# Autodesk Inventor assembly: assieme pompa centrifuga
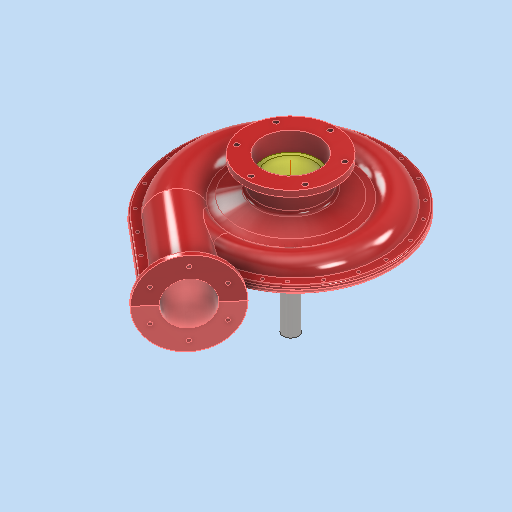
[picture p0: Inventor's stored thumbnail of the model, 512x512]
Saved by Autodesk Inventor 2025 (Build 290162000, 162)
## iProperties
Created: 2025-04
Part Number: assieme pompa centrifuga
Document SubType Name: Assembly
Designer: R5800u
Author: R5800u
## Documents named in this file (9)
- C:\Users\R5800u\Desktop\pompa centrifuga\assieme pompa centrifuga.iam
- C:\Users\R5800u\Desktop\pompa centrifuga\pompa centrifuga.ipt
- C:\Users\R5800u\Desktop\pompa centrifuga\cassa.ipt
- C:\Users\R5800u\Desktop\pompa centrifuga\cassa2.ipt
- C:\Users\R5800u\Desktop\pompa centrifuga\albero_20mm.ipt
- C:\Users\R5800u\Documents\Inventor\Content Center Files\R2025\it-IT\BS 290 SKF(30)\BS 290 SKF - SKF 6004.ipt
- C:\Users\R5800u\Documents\Inventor\Content Center Files\R2025\it-IT\DIN 7603 A\DIN 7603 - A20 x 24  (lt).ipt
- C:\Users\R5800u\Desktop\pompa centrifuga\oring 20mm.ipt
- C:\Users\R5800u\Documents\Inventor\Content Center Files\R2025\it-IT\AS 1420\AS 1420 - 1973 - M8 x 35.ipt
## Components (10 placed, 8 different names)
1. pompa centrifuga:1 — Coincidente:1, Allineato:1, Coincidente:6
2. cassa:1 — Coincidente:1, Allineato:1, Angolo:1, Coincidente:2, Coincidente:3, Allineato:2
3. cassa2:1 — Coincidente:2, Coincidente:3, Allineato:2, Allineato:3, Rotazionale:1, Rotazionale:3, Rotazionale:4
4. albero_20mm:1 — Coincidente:4
5. BS 290 SKF 6004:1 — Coincidente:4, Allineato:3
6. BS 290 SKF 6004:2 — Rotazionale:1, Rotazionale:2
7. DIN 7603 A A20 x 24  (lt):1 — Rotazionale:2
8. oring 20mm:1 — Rotazionale:3
9. oring 20mm:2 — Rotazionale:4
10. AS 1420 - Metrico M8 x 35:1 — Coincidente:6
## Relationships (13: Mate 5, RevoluteJoint 4, Flush 3, Angle 1)
- Coincidente:1 [Mate]: pompa centrifuga:1 ↔ cassa:1
- Allineato:1 [Flush]: pompa centrifuga:1 ↔ cassa:1
- Angolo:1 [Angle]: cassa:1
- Coincidente:2 [Mate]: cassa:1 ↔ cassa2:1
- Coincidente:3 [Mate]: cassa:1 ↔ cassa2:1
- Allineato:2 [Flush]: cassa:1 ↔ cassa2:1
- Coincidente:4 [Mate]: albero_20mm:1 ↔ BS 290 SKF 6004:1
- Allineato:3 [Flush]: cassa2:1 ↔ BS 290 SKF 6004:1
- Rotazionale:1 [RevoluteJoint]: cassa2:1 ↔ BS 290 SKF 6004:2
- Rotazionale:2 [RevoluteJoint]: BS 290 SKF 6004:2 ↔ DIN 7603 A A20 x 24  (lt):1
- Rotazionale:3 [RevoluteJoint]: cassa2:1 ↔ oring 20mm:1
- Rotazionale:4 [RevoluteJoint]: cassa2:1 ↔ oring 20mm:2
- Coincidente:6 [Mate]: pompa centrifuga:1 ↔ AS 1420 - Metrico M8 x 35:1
